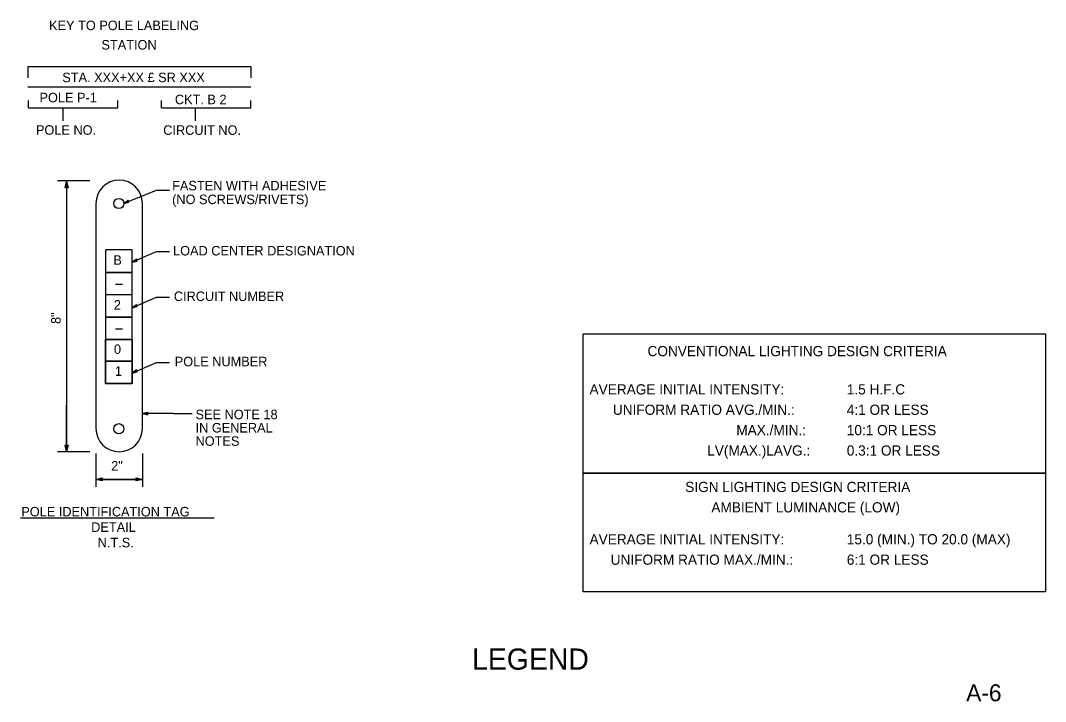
# Model space of a CAD drawing. Extents: x -1452 to -654, y -278 to 245.
# Drawn here: x -955.7 to -654.2, y -265.6 to -65.2 of the extents above; entities that cross this region are included whole.
import ezdxf

# ---------------------------------------------------------------- set-up
doc = ezdxf.new("R2010")
doc.units = 0
for name, color, linetype in [('Default', 7, 'Continuous'), ('NonPlottingEle_dp', 7, 'Continuous'), ('PlotBorder_dp', 7, 'Continuous'), ('SheetLines_dp', 7, 'Continuous')]:
    doc.layers.add(name, color=color, linetype=linetype)

msp = doc.modelspace()

# ---------------------------------------------------------------- linework, layer by layer
at = {"layer": 'PlotBorder_dp'}
for p, q in [((-953.56, -78.74), (-953.56, -82.05)), ((-953.56, -78.74), (-887.93, -78.74)), ((-887.93, -78.74), (-887.93, -82.05)), ((-953.56, -84.76), (-887.93, -84.76)), ((-953.31, -90.87), (-953.31, -88.73)), ((-927.04, -90.87), (-927.04, -88.73)), ((-914.2, -90.87), (-914.2, -88.73)), ((-887.93, -90.87), (-887.93, -88.73)), ((-953.31, -90.87), (-927.04, -90.87)), ((-943.23, -90.87), (-943.23, -94.69)), ((-914.2, -90.87), (-887.93, -90.87)), ((-904.3, -90.87), (-904.3, -94.69)), ((-944.84, -112.31), (-935.28, -112.31)), ((-942.62, -114.45), (-942.16, -112.57)), ((-941.67, -114.45), (-942.62, -114.45)), ((-942.16, -112.28), (-942.16, -192.04)), ((-942.16, -112.57), (-941.67, -114.45)), ((-915.78, -115.25), (-925.3, -119.05)), ((-911.84, -115.25), (-915.78, -115.25)), ((-933.52, -119.01), (-933.52, -185.31)), ((-924.02, -118.13), (-925.3, -119.05)), ((-924.02, -118.33), (-925.3, -119.05)), ((-924.02, -118.33), (-925.3, -119.05)), ((-925.3, -119.05), (-924.02, -118.33)), ((-925.3, -119.05), (-923.82, -118.5)), ((-925.3, -119.05), (-924.02, -118.5)), ((-924.02, -118.5), (-925.3, -119.05)), ((-925.3, -119.05), (-923.82, -118.69)), ((-923.82, -118.69), (-924.02, -118.13)), ((-924.02, -118.13), (-924.02, -118.33)), ((-923.82, -118.5), (-924.02, -118.33)), ((-924.02, -118.33), (-924.02, -118.33)), ((-924.02, -118.5), (-924.02, -118.33)), ((-924.02, -118.33), (-924.02, -118.5)), ((-924.02, -118.33), (-924.02, -118.5)), ((-919.85, -185.31), (-919.85, -119.01)), ((-930.73, -132.68), (-930.73, -172)), ((-922.84, -132.68), (-930.73, -132.68)), ((-922.84, -172), (-922.84, -132.68)), ((-915.78, -133.3), (-922.84, -136.36)), ((-921.56, -135.44), (-922.84, -136.36)), ((-921.56, -135.64), (-922.84, -136.36)), ((-921.56, -135.64), (-922.84, -136.36)), ((-922.84, -136.36), (-921.56, -135.64)), ((-921.37, -136), (-921.56, -135.44)), ((-921.56, -135.44), (-921.56, -135.64)), ((-921.37, -135.8), (-921.56, -135.64)), ((-921.56, -135.64), (-921.56, -135.64)), ((-921.56, -135.8), (-921.56, -135.64)), ((-921.56, -135.64), (-921.56, -135.8)), ((-921.56, -135.64), (-921.56, -135.8)), ((-911.84, -133.3), (-915.78, -133.3)), ((-922.84, -136.36), (-921.37, -135.8)), ((-922.84, -136.36), (-921.56, -135.8)), ((-921.56, -135.8), (-922.84, -136.36)), ((-922.84, -136.36), (-921.37, -136)), ((-922.84, -139.41), (-930.73, -139.41)), ((-922.84, -145.98), (-930.73, -145.98)), ((-915.78, -146.71), (-922.84, -149.8)), ((-911.84, -146.71), (-915.78, -146.71)), ((-921.56, -148.84), (-922.84, -149.8)), ((-921.56, -149.04), (-922.84, -149.8)), ((-921.56, -149.04), (-922.84, -149.8)), ((-922.84, -149.8), (-921.56, -149.04)), ((-922.84, -149.8), (-921.37, -149.24)), ((-922.84, -149.8), (-921.56, -149.24)), ((-921.56, -149.24), (-922.84, -149.8)), ((-922.84, -149.8), (-921.37, -149.4)), ((-921.37, -149.4), (-921.56, -148.84)), ((-921.56, -148.84), (-921.56, -149.04)), ((-921.37, -149.24), (-921.56, -149.04)), ((-921.56, -149.04), (-921.56, -149.04)), ((-921.56, -149.24), (-921.56, -149.04)), ((-921.56, -149.04), (-921.56, -149.24)), ((-921.56, -149.04), (-921.56, -149.24)), ((-922.84, -152.52), (-930.73, -152.52)), ((-922.84, -159.09), (-930.73, -159.09)), ((-922.84, -165.46), (-930.73, -165.46)), ((-915.78, -165.92), (-922.84, -168.98)), ((-921.56, -168.06), (-922.84, -168.98)), ((-921.56, -168.22), (-922.84, -168.98)), ((-921.56, -168.22), (-922.84, -168.98)), ((-922.84, -168.98), (-921.56, -168.22)), ((-922.84, -168.98), (-921.37, -168.42)), ((-922.84, -168.98), (-921.56, -168.42)), ((-921.56, -168.42), (-922.84, -168.98)), ((-922.84, -168.98), (-921.37, -168.62)), ((-921.37, -168.62), (-921.56, -168.06)), ((-921.56, -168.06), (-921.56, -168.22)), ((-921.37, -168.42), (-921.56, -168.22)), ((-921.56, -168.22), (-921.56, -168.22)), ((-921.56, -168.42), (-921.56, -168.22)), ((-921.56, -168.22), (-921.56, -168.42)), ((-921.56, -168.22), (-921.56, -168.42)), ((-911.84, -165.92), (-915.78, -165.92)), ((-922.84, -172), (-930.73, -172)), ((-930.73, -172), (-922.84, -172)), ((-942.16, -192.04), (-942.16, -178.38)), ((-918.29, -180.57), (-919.85, -180.91)), ((-918.29, -180.57), (-919.85, -180.91)), ((-918.26, -180.85), (-919.85, -180.91)), ((-919.85, -180.91), (-918.26, -180.85)), ((-918.26, -180.85), (-919.85, -180.91)), ((-919.85, -180.91), (-918.26, -180.85)), ((-910.81, -180.91), (-919.85, -180.91)), ((-919.85, -180.91), (-918.27, -181.27)), ((-919.85, -180.91), (-918.34, -181)), ((-918.34, -181), (-918.29, -180.57)), ((-918.3, -180.57), (-918.3, -180.57)), ((-918.27, -181.27), (-918.29, -180.57)), ((-918.29, -180.57), (-918.26, -180.85)), ((-918.27, -180.85), (-918.27, -180.85)), ((-918.27, -180.85), (-918.27, -180.85)), ((-918.27, -180.85), (-918.27, -180.85)), ((-910.81, -180.91), (-905.19, -180.91)), ((-944.84, -192.08), (-935.28, -192.08)), ((-942.16, -192.04), (-942.62, -190.17)), ((-942.62, -190.17), (-941.67, -190.17)), ((-941.67, -190.17), (-942.16, -192.04)), ((-933.52, -192.68), (-933.52, -202.43)), ((-926.79, -192.04), (-926.79, -192.04)), ((-919.85, -192.68), (-919.85, -202.43)), ((-933.52, -200.25), (-931.65, -199.79)), ((-919.85, -200.25), (-933.52, -200.25)), ((-933.52, -200.25), (-919.85, -200.25)), ((-931.65, -200.71), (-933.52, -200.25)), ((-931.65, -199.79), (-931.65, -200.71)), ((-921.73, -199.79), (-919.85, -200.25)), ((-921.73, -200.71), (-921.73, -199.79)), ((-919.85, -200.25), (-921.73, -200.71)), ((-955.71, -211.55), (-898.77, -211.55))]:
    msp.add_line(p, q, dxfattribs=at)
for points in [[(-930.73, -139.41), (-922.84, -139.41), (-922.84, -132.68), (-930.73, -132.68)], [(-930.73, -152.52), (-922.84, -152.52), (-922.84, -145.98), (-930.73, -145.98)], [(-930.73, -159.09), (-922.84, -159.09), (-922.84, -165.46), (-930.73, -165.46)], [(-930.73, -165.46), (-922.84, -165.46), (-922.84, -172), (-930.73, -172)]]:
    msp.add_lwpolyline(points, close=True, dxfattribs=at)
for points in [[(-927.77, -142.83), (-925.7, -142.83)], [(-927.77, -155.94), (-925.7, -155.94)]]:
    msp.add_lwpolyline(points, dxfattribs=at)
for centre in [(-926.8, -119.05), (-926.8, -185.34)]:
    msp.add_circle(centre, 1.5, dxfattribs=at)
for centre, start, end in [((-926.69, -119.01), 0, 180), ((-926.69, -185.31), 180, 0)]:
    msp.add_arc(centre, 6.83, start, end, dxfattribs=at)
at = {"layer": 'SheetLines_dp'}
for points in [[(-790.22, -157.37), (-654.17, -157.37), (-654.17, -198.41), (-790.22, -198.41)], [(-790.22, -198.41), (-654.17, -198.41), (-654.17, -233.32), (-790.22, -233.32)]]:
    msp.add_lwpolyline(points, close=True, dxfattribs=at)

# ---------------------------------------------------------------- texts
at = {"layer": 'Default'}
msp.add_text('CONVENTIONAL LIGHTING DESIGN CRITERIA', height=3, dxfattribs=at).set_placement((-771.26, -164))
at = {"layer": 'NonPlottingEle_dp'}
msp.add_text('A-6', height=5, dxfattribs=at).set_placement((-677.51, -265.57))
at = {"layer": 'PlotBorder_dp'}
for s, height, p in [('KEY TO POLE LABELING', 2.8, (-947.3, -68.03)), ('STATION', 2.8, (-931.89, -73.74)), ('STA. XXX+XX £ SR XXX', 2.8, (-943.42, -83.34)), ('POLE P-1', 2.8, (-950.12, -89.27)), ('CKT. B 2', 2.8, (-910.29, -89.84)), ('POLE NO.', 2.8, (-951.17, -98.82)), ('CIRCUIT NO.', 2.8, (-913.72, -98.85)), ('FASTEN WITH ADHESIVE', 2.8, (-911.1, -115.19)), ('(NO SCREWS/RIVETS)', 2.8, (-911.1, -119.24)), ('LOAD CENTER DESIGNATION', 2.8, (-910.82, -134.35)), ('B', 2.8, (-928.4, -137.1)), ('2', 2.8, (-928.25, -150.3)), ('CIRCUIT NUMBER', 2.8, (-910.59, -147.76)), ('0', 2.8, (-928.21, -163.33)), ('POLE NUMBER', 2.8, (-910.33, -166.97)), ('1', 2.8, (-927.94, -169.78)), ('AVERAGE INITIAL INTENSITY:', 3, (-788.31, -175.26)), ('1.5 H.F.C', 3, (-712.63, -175.26)), ('SEE NOTE 18', 2.8, (-904.21, -182.54)), ('UNIFORM RATIO AVG./MIN.:', 3, (-781.44, -181.26)), ('4:1 OR LESS', 3, (-712.63, -181.26)), ('IN GENERAL ', 2.8, (-904.21, -186.46)), ('MAX./MIN.:', 3, (-745.13, -187.26)), ('10:1 OR LESS', 3, (-712.63, -187.26)), ('NOTES', 2.8, (-904.21, -190.38)), ('LV(MAX.)LAVG.:', 3, (-753.7, -193.26)), ('0.3:1 OR LESS', 3, (-712.63, -193.26)), ('2"', 2.8, (-929.04, -197.67)), ('SIGN LIGHTING DESIGN CRITERIA', 3, (-760.16, -203.98)), ('AMBIENT LUMINANCE (LOW)', 3, (-752.47, -209.98)), ('POLE IDENTIFICATION TAG ', 2.8, (-955.47, -211.16)), ('DETAIL', 2.8, (-934.9, -215.71)), ('AVERAGE INITIAL INTENSITY:', 3, (-788.31, -219.39)), ('15.0 (MIN.) TO 20.0 (MAX)', 3, (-712.63, -219.39)), ('N.T.S.', 2.8, (-933.01, -220.26)), ('UNIFORM RATIO MAX./MIN.:', 3, (-782.09, -225.39)), ('6:1 OR LESS', 3, (-712.63, -225.39)), ('            LEGEND             ', 6.25, (-850.74, -256.28))]:
    msp.add_text(s, height=height, dxfattribs=at).set_placement(p)
msp.add_text('8"', height=2.8, rotation=90, dxfattribs=at).set_placement((-943.91, -154.51))

doc.saveas('drawing.dxf')
